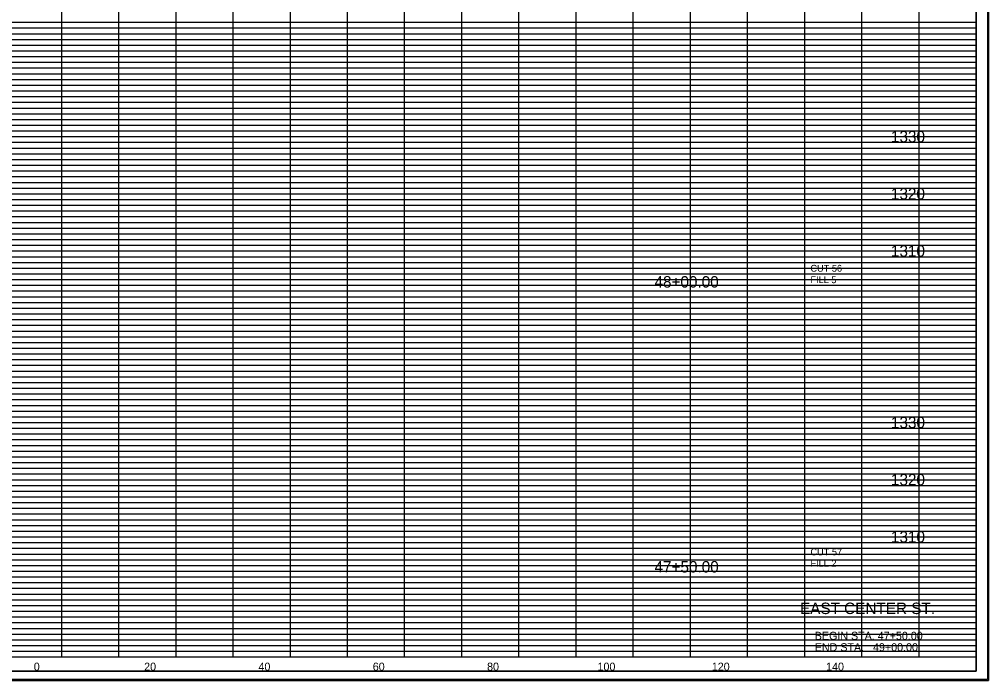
# Model space of a CAD drawing. Extents: x 980 to 1324, y 978 to 1767.
# Drawn here: x 1152.6 to 1322.2, y 1265.9 to 1381.5 of the extents above; entities that cross this region are included whole.
import ezdxf

# ---------------------------------------------------------------- set-up
doc = ezdxf.new("R2010")
doc.units = 0
for name, color, linetype in [('DESIGN - SHEET - Corner Text', 7, 'Continuous'), ('DESIGN - SHEET - Light Grid', 7, 'Continuous'), ('DESIGN - SHEET - Linework', 7, 'Continuous'), ('DESIGN - SHEET - Plot Shape', 7, 'Continuous'), ('DESIGN - TYPICAL - Text', 7, 'Continuous')]:
    doc.layers.add(name, color=color, linetype=linetype)

# ---------------------------------------------------------------- blocks, each defined once
blk = doc.blocks.new('XSTSHT')
at = {"layer": 'DESIGN - SHEET - Light Grid'}
for p, q in [((8, 11.1), (16, 11.1)), ((16, 11.1), (24, 11.1)), ((24, 11.1), (32, 11.1)), ((8, 10.9), (16, 10.9)), ((16, 10.9), (24, 10.9)), ((24, 10.9), (32, 10.9)), ((8, 10.8), (16, 10.8)), ((8, 10.7), (16, 10.7)), ((16, 10.8), (24, 10.8)), ((16, 10.7), (24, 10.7)), ((24, 10.8), (32, 10.8)), ((24, 10.7), (32, 10.7)), ((8, 10.6), (16, 10.6)), ((16, 10.6), (24, 10.6)), ((24, 10.6), (32, 10.6)), ((8, 10.5), (16, 10.5)), ((8, 10.4), (16, 10.4)), ((16, 10.5), (24, 10.5)), ((16, 10.4), (24, 10.4)), ((24, 10.5), (32, 10.5)), ((24, 10.4), (32, 10.4)), ((8, 10.3), (16, 10.3)), ((8, 10.2), (16, 10.2)), ((16, 10.3), (24, 10.3)), ((16, 10.2), (24, 10.2)), ((24, 10.3), (32, 10.3)), ((24, 10.2), (32, 10.2)), ((8, 10.1), (16, 10.1)), ((16, 10.1), (24, 10.1)), ((24, 10.1), (32, 10.1)), ((8, 9.9), (16, 9.9)), ((16, 9.9), (24, 9.9)), ((24, 9.9), (32, 9.9)), ((8, 9.8), (16, 9.8)), ((8, 9.7), (16, 9.7)), ((16, 9.8), (24, 9.8)), ((16, 9.7), (24, 9.7)), ((24, 9.8), (32, 9.8)), ((24, 9.7), (32, 9.7)), ((8, 9.6), (16, 9.6)), ((8, 9.5), (16, 9.5)), ((16, 9.6), (24, 9.6)), ((16, 9.5), (24, 9.5)), ((24, 9.6), (32, 9.6)), ((24, 9.5), (32, 9.5)), ((8, 9.4), (16, 9.4)), ((16, 9.4), (24, 9.4)), ((24, 9.4), (32, 9.4)), ((8, 9.3), (16, 9.3)), ((8, 9.2), (16, 9.2)), ((16, 9.3), (24, 9.3)), ((16, 9.2), (24, 9.2)), ((24, 9.3), (32, 9.3)), ((24, 9.2), (32, 9.2)), ((8, 9.1), (16, 9.1)), ((16, 9.1), (24, 9.1)), ((24, 9.1), (32, 9.1)), ((8, 8.9), (16, 8.9)), ((16, 8.9), (24, 8.9)), ((24, 8.9), (32, 8.9)), ((8, 8.8), (16, 8.8)), ((8, 8.7), (16, 8.7)), ((16, 8.8), (24, 8.8)), ((16, 8.7), (24, 8.7)), ((24, 8.8), (32, 8.8)), ((24, 8.7), (32, 8.7)), ((8, 8.6), (16, 8.6)), ((8, 8.5), (16, 8.5)), ((16, 8.6), (24, 8.6)), ((16, 8.5), (24, 8.5)), ((24, 8.6), (32, 8.6)), ((24, 8.5), (32, 8.5)), ((8, 8.4), (16, 8.4)), ((16, 8.4), (24, 8.4)), ((24, 8.4), (32, 8.4)), ((8, 8.3), (16, 8.3)), ((8, 8.2), (16, 8.2)), ((16, 8.3), (24, 8.3)), ((16, 8.2), (24, 8.2)), ((24, 8.3), (32, 8.3)), ((24, 8.2), (32, 8.2)), ((8, 8.1), (16, 8.1)), ((16, 8.1), (24, 8.1)), ((24, 8.1), (32, 8.1)), ((8, 7.9), (16, 7.9)), ((16, 7.9), (24, 7.9)), ((24, 7.9), (32, 7.9)), ((8, 7.8), (16, 7.8)), ((8, 7.7), (16, 7.7)), ((16, 7.8), (24, 7.8)), ((16, 7.7), (24, 7.7)), ((24, 7.8), (32, 7.8)), ((24, 7.7), (32, 7.7)), ((8, 7.6), (16, 7.6)), ((8, 7.5), (16, 7.5)), ((16, 7.6), (24, 7.6)), ((16, 7.5), (24, 7.5)), ((24, 7.6), (32, 7.6)), ((24, 7.5), (32, 7.5)), ((8, 7.4), (16, 7.4)), ((8, 7.3), (16, 7.3)), ((16, 7.4), (24, 7.4)), ((16, 7.3), (24, 7.3)), ((24, 7.4), (32, 7.4)), ((24, 7.3), (32, 7.3)), ((8, 7.2), (16, 7.2)), ((16, 7.2), (24, 7.2)), ((24, 7.2), (32, 7.2)), ((8, 7.1), (16, 7.1)), ((16, 7.1), (24, 7.1)), ((24, 7.1), (32, 7.1)), ((8, 6.9), (16, 6.9)), ((8, 6.8), (16, 6.8)), ((16, 6.9), (24, 6.9)), ((16, 6.8), (24, 6.8)), ((24, 6.9), (32, 6.9)), ((24, 6.8), (32, 6.8)), ((8, 6.7), (16, 6.7)), ((16, 6.7), (24, 6.7)), ((24, 6.7), (32, 6.7)), ((8, 6.6), (16, 6.6)), ((8, 6.5), (16, 6.5)), ((16, 6.6), (24, 6.6)), ((16, 6.5), (24, 6.5)), ((24, 6.6), (32, 6.6)), ((24, 6.5), (32, 6.5)), ((8, 6.4), (16, 6.4)), ((8, 6.3), (16, 6.3)), ((16, 6.4), (24, 6.4)), ((16, 6.3), (24, 6.3)), ((24, 6.4), (32, 6.4)), ((24, 6.3), (32, 6.3)), ((8, 6.2), (16, 6.2)), ((16, 6.2), (24, 6.2)), ((24, 6.2), (32, 6.2)), ((8, 6.1), (16, 6.1)), ((16, 6.1), (24, 6.1)), ((24, 6.1), (32, 6.1)), ((8, 5.9), (16, 5.9)), ((8, 5.8), (16, 5.8)), ((16, 5.9), (24, 5.9)), ((16, 5.8), (24, 5.8)), ((24, 5.9), (32, 5.9)), ((24, 5.8), (32, 5.8)), ((8, 5.7), (16, 5.7)), ((8, 5.6), (16, 5.6)), ((16, 5.7), (24, 5.7)), ((16, 5.6), (24, 5.6)), ((24, 5.7), (32, 5.7)), ((24, 5.6), (32, 5.6)), ((8, 5.5), (16, 5.5)), ((16, 5.5), (24, 5.5)), ((24, 5.5), (32, 5.5)), ((8, 5.4), (16, 5.4)), ((8, 5.3), (16, 5.3)), ((16, 5.4), (24, 5.4)), ((16, 5.3), (24, 5.3)), ((24, 5.4), (32, 5.4)), ((24, 5.3), (32, 5.3)), ((8, 5.2), (16, 5.2)), ((8, 5.1), (16, 5.1)), ((16, 5.2), (24, 5.2)), ((16, 5.1), (24, 5.1)), ((24, 5.2), (32, 5.2)), ((24, 5.1), (32, 5.1)), ((8, 4.9), (16, 4.9)), ((8, 4.8), (16, 4.8)), ((16, 4.9), (24, 4.9)), ((16, 4.8), (24, 4.8)), ((24, 4.9), (32, 4.9)), ((24, 4.8), (32, 4.8)), ((8, 4.7), (16, 4.7)), ((8, 4.6), (16, 4.6)), ((16, 4.7), (24, 4.7)), ((16, 4.6), (24, 4.6)), ((24, 4.7), (32, 4.7)), ((24, 4.6), (32, 4.6)), ((8, 4.5), (16, 4.5)), ((16, 4.5), (24, 4.5)), ((24, 4.5), (32, 4.5)), ((8, 4.4), (16, 4.4)), ((8, 4.3), (16, 4.3)), ((16, 4.4), (24, 4.4)), ((16, 4.3), (24, 4.3)), ((24, 4.4), (32, 4.4)), ((24, 4.3), (32, 4.3)), ((8, 4.2), (16, 4.2)), ((8, 4.1), (16, 4.1)), ((16, 4.2), (24, 4.2)), ((16, 4.1), (24, 4.1)), ((24, 4.2), (32, 4.2)), ((24, 4.1), (32, 4.1)), ((8, 3.9), (16, 3.9)), ((8, 3.8), (16, 3.8)), ((16, 3.9), (24, 3.9)), ((16, 3.8), (24, 3.8)), ((24, 3.9), (32, 3.9)), ((24, 3.8), (32, 3.8)), ((8, 3.7), (16, 3.7)), ((8, 3.6), (16, 3.6)), ((16, 3.7), (24, 3.7)), ((16, 3.6), (24, 3.6)), ((24, 3.7), (32, 3.7)), ((24, 3.6), (32, 3.6)), ((8, 3.5), (16, 3.5)), ((8, 3.4), (16, 3.4)), ((16, 3.5), (24, 3.5)), ((16, 3.4), (24, 3.4)), ((24, 3.5), (32, 3.5)), ((24, 3.4), (32, 3.4)), ((8, 3.3), (16, 3.3)), ((16, 3.3), (24, 3.3)), ((24, 3.3), (32, 3.3)), ((8, 3.2), (16, 3.2)), ((8, 3.1), (16, 3.1)), ((16, 3.2), (24, 3.2)), ((16, 3.1), (24, 3.1)), ((24, 3.2), (32, 3.2)), ((24, 3.1), (32, 3.1)), ((8, 2.9), (16, 2.9)), ((16, 2.9), (24, 2.9)), ((24, 2.9), (32, 2.9)), ((8, 2.8), (16, 2.8)), ((16, 2.8), (24, 2.8)), ((24, 2.8), (32, 2.8)), ((8, 2.7), (16, 2.7)), ((8, 2.6), (16, 2.6)), ((16, 2.7), (24, 2.7)), ((16, 2.6), (24, 2.6)), ((24, 2.7), (32, 2.7)), ((24, 2.6), (32, 2.6)), ((8, 2.5), (16, 2.5)), ((8, 2.4), (16, 2.4)), ((16, 2.5), (24, 2.5)), ((16, 2.4), (24, 2.4)), ((24, 2.5), (32, 2.5)), ((24, 2.4), (32, 2.4)), ((8, 2.3), (16, 2.3)), ((16, 2.3), (24, 2.3)), ((24, 2.3), (32, 2.3)), ((8, 2.2), (16, 2.2)), ((8, 2.1), (16, 2.1)), ((16, 2.2), (24, 2.2)), ((16, 2.1), (24, 2.1)), ((24, 2.2), (32, 2.2)), ((24, 2.1), (32, 2.1)), ((8, 1.9), (16, 1.9)), ((16, 1.9), (24, 1.9)), ((24, 1.9), (32, 1.9)), ((8, 1.8), (16, 1.8)), ((8, 1.7), (16, 1.7)), ((16, 1.8), (24, 1.8)), ((16, 1.7), (24, 1.7)), ((24, 1.8), (32, 1.8)), ((24, 1.7), (32, 1.7)), ((8, 1.6), (16, 1.6)), ((16, 1.6), (24, 1.6)), ((24, 1.6), (32, 1.6)), ((8, 1.5), (16, 1.5)), ((8, 1.4), (16, 1.4)), ((16, 1.5), (24, 1.5)), ((16, 1.4), (24, 1.4)), ((24, 1.5), (32, 1.5)), ((24, 1.4), (32, 1.4)), ((8, 1.3), (16, 1.3)), ((8, 1.2), (16, 1.2)), ((16, 1.3), (24, 1.3)), ((16, 1.2), (24, 1.2)), ((24, 1.3), (32, 1.3)), ((24, 1.2), (32, 1.2)), ((8, 1.1), (16, 1.1)), ((16, 1.1), (24, 1.1)), ((24, 1.1), (32, 1.1)), ((8, 0.9), (16, 0.9)), ((16, 0.9), (24, 0.9)), ((24, 0.9), (32, 0.9)), ((8, 0.8), (16, 0.8)), ((8, 0.7), (16, 0.7)), ((16, 0.8), (24, 0.8)), ((16, 0.7), (24, 0.7)), ((24, 0.8), (32, 0.8)), ((24, 0.7), (32, 0.7)), ((8, 0.6), (16, 0.6)), ((16, 0.6), (24, 0.6)), ((24, 0.6), (32, 0.6)), ((8, 0.5), (16, 0.5)), ((8, 0.4), (16, 0.4)), ((16, 0.5), (24, 0.5)), ((16, 0.4), (24, 0.4)), ((24, 0.5), (32, 0.5)), ((24, 0.4), (32, 0.4)), ((8, 0.3), (16, 0.3)), ((8, 0.2), (16, 0.2)), ((16, 0.3), (24, 0.3)), ((16, 0.2), (24, 0.2)), ((24, 0.3), (32, 0.3)), ((24, 0.2), (32, 0.2)), ((8, 0.1), (16, 0.1)), ((16, 0.1), (24, 0.1)), ((24, 0.1), (32, 0.1))]:
    blk.add_line(p, q, dxfattribs=at)
at = {"layer": 'DESIGN - SHEET - Linework'}
for p, q in [((32.217, 21.414), (32.217, -0.414)), ((16, 0), (16, 21)), ((17, 0), (17, 21)), ((18, 0), (18, 21)), ((19, 0), (19, 21)), ((20, 0), (20, 21)), ((21, 0), (21, 21)), ((22, 0), (22, 21)), ((23, 0), (23, 21)), ((24, 0), (24, 21)), ((25, 0), (25, 21)), ((26, 0), (26, 21)), ((27, 0), (27, 21)), ((28, 0), (28, 20)), ((29, 0), (29, 20)), ((30, 0), (30, 20)), ((31, 0), (31, 20)), ((0, 11), (32, 11)), ((0, 10), (32, 10)), ((0, 9), (32, 9)), ((0, 8), (32, 8)), ((0, 7), (32, 7)), ((0, 6), (32, 6)), ((0, 5), (32, 5)), ((0, 4), (32, 4)), ((0, 3), (32, 3)), ((0, 2), (32, 2)), ((0, 1), (32, 1)), ((-1.823, -0.414), (32.217, -0.414))]:
    blk.add_line(p, q, dxfattribs=at)
blk.add_lwpolyline([(0, 21), (0, 0), (32, 0), (32, 21), (0, 21)], dxfattribs=at)
at = {"layer": 'DESIGN - SHEET - Plot Shape'}
for points in [[(-1.803, 21.394), (32.197, 21.394), (32.197, -0.394), (-1.803, -0.394)], [(-0.85, 21), (32, 21), (32, -0.25), (-0.85, -0.25)]]:
    blk.add_lwpolyline(points, close=True, dxfattribs=at)

msp = doc.modelspace()

# ---------------------------------------------------------------- linework, layer by layer
at = {"layer": 'DESIGN - SHEET - Plot Shape'}
msp.add_lwpolyline([(991.5, 1267.5), (1320, 1267.5), (1320, 1480), (991.5, 1480)], close=True, dxfattribs=at)

# ---------------------------------------------------------------- block references
at = {"layer": 'DESIGN - SHEET - Plot Shape', "xscale": 10, "yscale": 10}
msp.add_blockref('XSTSHT', (1000, 1270), dxfattribs=at)

# ---------------------------------------------------------------- texts
at = {"layer": 'DESIGN - SHEET - Corner Text'}
for s, height, p in [('EAST CENTER ST.', 2, (1289.17, 1277.5)), ('BEGIN STA. 47+50.00', 1.4, (1291.75, 1273)), ('END STA.   49+00.00', 1.4, (1291.75, 1271))]:
    msp.add_text(s, height=height, dxfattribs=at).set_placement(p)
at = {"layer": 'DESIGN - TYPICAL - Text'}
for s, height, p in [('     1330     ', 2, (1301.37, 1360)), ('     1320     ', 2, (1301.37, 1350)), ('     1310     ', 2, (1301.37, 1340)), ('CUT 56', 1.2, (1291, 1337.37)), ('     48+00.00     ', 2, (1260, 1334.6)), ('FILL 5', 1.2, (1291, 1335.37)), ('     1330     ', 2, (1301.37, 1310)), ('     1320     ', 2, (1301.37, 1300)), ('     1310     ', 2, (1301.37, 1290)), ('CUT 57', 1.2, (1291, 1287.77)), ('     47+50.00     ', 2, (1260, 1284.77)), ('FILL 2', 1.2, (1291, 1285.77)), ('     0     ', 1.4, (1152.51, 1267.6)), ('     0     ', 1.4, (1152.51, 1267.6)), ('     20     ', 1.4, (1171.82, 1267.6)), ('     40     ', 1.4, (1191.82, 1267.6)), ('     60     ', 1.4, (1211.82, 1267.6)), ('     80     ', 1.4, (1231.82, 1267.6)), ('     100     ', 1.4, (1251.14, 1267.6)), ('     120     ', 1.4, (1271.14, 1267.6)), ('     140     ', 1.4, (1291.14, 1267.6))]:
    msp.add_text(s, height=height, dxfattribs=at).set_placement(p)

doc.saveas('drawing.dxf')
